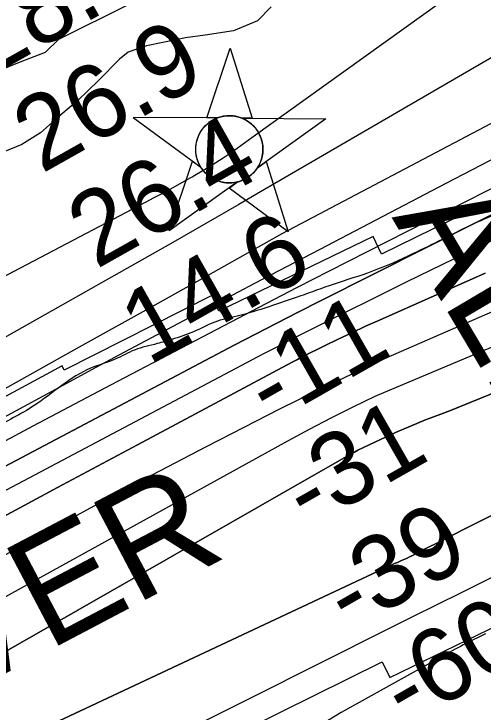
# Model space of a CAD drawing. Extents: x 3324104 to 3361979, y 612876 to 638273.
# Drawn here: x 3355279 to 3355706, y 622268 to 622903 of the extents above; entities that cross this region are included whole.
import ezdxf

# ---------------------------------------------------------------- set-up
doc = ezdxf.new("R2010")
doc.units = 0
for name, color, linetype in [('V-CHAN-NAID', 7, 'Continuous'), ('V-RIVR-EDGE', 7, 'Continuous'), ('V-RIVR-RANG', 7, 'Continuous'), ('V-RRAP-RVMT', 7, 'Continuous'), ('V-RRAP-RVMT-IDEN', 7, 'Continuous'), ('V-TOPO-DPTH', 7, 'Continuous'), ('V-TOPO-MAJR', 7, 'Continuous'), ('V-TOPO-MINR', 7, 'Continuous'), ('V-TOPO-WATR', 7, 'Continuous'), ('V-WETL-SWMP', 7, 'Continuous')]:
    doc.layers.add(name, color=color, linetype=linetype)

msp = doc.modelspace()

# ---------------------------------------------------------------- linework, layer by layer
at = {"layer": 'V-CHAN-NAID'}
for points in [[(3355464.16, 622808.58), (3355454.57, 622808.65), (3355475.7, 622872.14), (3355495.92, 622808.36), (3355486.34, 622808.43), (3355484.76, 622809.01), (3355482.67, 622809.63), (3355480.62, 622810.08), (3355478.59, 622810.38), (3355477.42, 622810.5), (3355475.89, 622810.58), (3355474.17, 622810.58), (3355472.8, 622810.51), (3355470.89, 622810.31), (3355469.52, 622810.09), (3355467.74, 622809.7), (3355466.21, 622809.28), (3355465.18, 622808.95)], [(3355464.16, 622808.58), (3355387.67, 622809.13), (3355449.23, 622763.73), (3355448.12, 622765.64), (3355447.31, 622767.26), (3355446.49, 622769.23), (3355445.79, 622771.29), (3355445.43, 622772.61), (3355445.06, 622774.24), (3355444.82, 622775.68), (3355444.63, 622777.28), (3355444.52, 622779.01), (3355444.51, 622780.6), (3355444.62, 622782.67), (3355444.8, 622784.29), (3355445.19, 622786.49), (3355445.68, 622788.41), (3355446.28, 622790.3), (3355446.93, 622791.98), (3355447.66, 622793.57), (3355448.47, 622795.1), (3355449.54, 622796.84), (3355450.57, 622798.31), (3355451.57, 622799.58), (3355452.57, 622800.72), (3355453.88, 622802.06), (3355454.93, 622803.03), (3355456.65, 622804.42), (3355457.86, 622805.29), (3355459.54, 622806.36), (3355461.27, 622807.31), (3355462.72, 622807.99)], [(3355486.34, 622808.43), (3355562.83, 622807.88), (3355500.63, 622763.36), (3355501.54, 622764.85), (3355502.52, 622766.7), (3355503.23, 622768.28), (3355503.97, 622770.24), (3355504.51, 622772.02), (3355504.91, 622773.66), (3355505.27, 622775.67), (3355505.46, 622777.25), (3355505.58, 622779.45), (3355505.55, 622781.51), (3355505.37, 622783.73), (3355505.1, 622785.49), (3355504.61, 622787.72), (3355503.97, 622789.86), (3355503.22, 622791.85), (3355502.57, 622793.29), (3355501.56, 622795.2), (3355500.5, 622796.93), (3355499.29, 622798.63), (3355498.03, 622800.17), (3355496.75, 622801.53), (3355495.12, 622803.07), (3355493.38, 622804.48), (3355491.7, 622805.65), (3355489.81, 622806.79), (3355488.34, 622807.55)], [(3355482.6, 622750.46), (3355420.39, 622705.93), (3355441.52, 622769.42), (3355449.23, 622763.73), (3355449.87, 622762.76), (3355451.25, 622760.9), (3355452.47, 622759.49), (3355453.93, 622757.99), (3355455.32, 622756.73), (3355456.77, 622755.58), (3355458.18, 622754.59), (3355459.86, 622753.56), (3355461.57, 622752.64), (3355463.36, 622751.83), (3355464.81, 622751.28), (3355466.44, 622750.75), (3355468.66, 622750.18), (3355470.19, 622749.9), (3355472.22, 622749.64), (3355473.75, 622749.54), (3355475.62, 622749.51), (3355477.31, 622749.59), (3355479.02, 622749.77), (3355480.92, 622750.08)], [(3355500.63, 622763.36), (3355508.42, 622768.94), (3355528.65, 622705.17), (3355474.8, 622744.88), (3355482.6, 622750.46), (3355484.26, 622750.93), (3355485.87, 622751.49), (3355488.03, 622752.41), (3355489.77, 622753.29), (3355491.63, 622754.4), (3355493.37, 622755.62), (3355494.92, 622756.86), (3355496.21, 622758.03), (3355497.59, 622759.45), (3355498.8, 622760.85), (3355499.92, 622762.32)]]:
    msp.add_lwpolyline(points, close=True, dxfattribs=at)
msp.add_circle((3355475.05, 622780.05), 30.54, dxfattribs=at)
at = {"layer": 'V-RIVR-EDGE'}
msp.add_spline([(3356051.95, 622889.63), (3356029.15, 622881.43), (3356012.46, 622875.66), (3355994.6, 622867.17), (3355977.52, 622859.07), (3355958.5, 622850.97), (3355948.4, 622843.24), (3355934.03, 622834.75), (3355904.12, 622817.76), (3355878.1, 622802.31), (3355856.74, 622790.34), (3355829.95, 622776.44), (3355805.11, 622765.65), (3355764.72, 622744.81), (3355744.14, 622733.61), (3355694.06, 622710.85), (3355668.43, 622698.12), (3355641.64, 622685), (3355605.15, 622669.19), (3355569.44, 622657.26), (3355539.17, 622646.47), (3355510.83, 622636.85), (3355482.11, 622628.39), (3355461.93, 622623.01), (3355442.52, 622614.14), (3355422.73, 622607.21), (3355409.53, 622603.36), (3355388.97, 622597.59), (3355371.88, 622589.49), (3355348.98, 622581.02), (3355297.71, 622547.02), (3355260.04, 622525.78), (3355211.1, 622494.49), (3355190.13, 622484.46), (3355184.7, 622482.92), (3355179.26, 622477.89), (3355174.21, 622475.58), (3355160.62, 622470.96), (3355143.54, 622463.63), (3355133.06, 622457.07), (3355125.67, 622450.49), (3355113.25, 622443.93), (3355096.93, 622433.11), (3355081.02, 622426.95), (3355064.32, 622419.23), (3355056.95, 622418.86), (3355048.8, 622414.62), (3355041.8, 622406.88), (3355036.76, 622406.5), (3355031.32, 622405.74), (3355027.05, 622404.2), (3355017.34, 622396.08), (3355010.74, 622394.93), (3355001.42, 622388.36), (3354988.6, 622379.09), (3354972.29, 622369.43), (3354947.44, 622356.31), (3354937.73, 622351.68), (3354926.08, 622343.56), (3354903.15, 622326.56), (3354891.11, 622318.06), (3354883.33, 622307.22), (3354879.44, 622304.12), (3354875.17, 622302.58), (3354867.8, 622299.11), (3354853.03, 622288.29), (3354842.54, 622279.01), (3354826.61, 622267.41), (3354807.2, 622259.71), (3354793.23, 622255.47), (3354765.68, 622249.73), (3354748.61, 622245.5), (3354734.63, 622239.33), (3354712.11, 622227.37), (3354697.74, 622218.87), (3354685.31, 622209.98), (3354640.65, 622184.5), (3354622.01, 622176.01), (3354616.19, 622175.25), (3354603.38, 622167.52), (3354578.92, 622157.11), (3354554.46, 622147.48), (3354537.39, 622142.87), (3354530.78, 622137.84), (3354500.11, 622122.79), (3354463.61, 622102.33), (3354417.79, 622078.79), (3354386.33, 622060.64), (3354340.11, 622032.44), (3354321.08, 622021.25), (3354284.96, 621998.84), (3354257, 621982.24), (3354217, 621958.68), (3354194.08, 621942.84), (3354176.99, 621931.63), (3354157.57, 621921.98), (3354141.64, 621910.39), (3354135.42, 621904.2), (3354130.36, 621897.62), (3354120.65, 621891.05), (3354103.96, 621882.95), (3354075.58, 621856.65), (3354044.89, 621835.39), (3354013.04, 621812.21), (3353971.47, 621781.67), (3353947.77, 621763.5), (3353941.17, 621763.52), (3353935.35, 621762.76), (3353929.53, 621760.06), (3353924.87, 621756.58), (3353920.59, 621751.55), (3353917.08, 621742.64), (3353910.48, 621741.49), (3353904.66, 621738.4), (3353893.78, 621731.06), (3353879.8, 621721.4), (3353866.19, 621708.64), (3353854.92, 621697.42), (3353843.26, 621687.75), (3353839.77, 621688.54), (3353831.23, 621686.23), (3353823.08, 621681.21), (3353818.03, 621677.34), (3353800.94, 621666.14), (3353790.85, 621663.06), (3353781.91, 621654.94), (3353777.63, 621651.85), (3353776.07, 621648.75), (3353775.67, 621643.71), (3353772.18, 621641), (3353755.87, 621632.13), (3353735.68, 621622.09), (3353718.58, 621608.17), (3353704.21, 621600.45), (3353694.12, 621596.6), (3353683.64, 621592.36), (3353671.21, 621584.25), (3353642.07, 621562.99), (3353598.95, 621534.01), (3353578.37, 621522.43), (3353556.23, 621507.75), (3353547.68, 621501.95), (3353525.93, 621489.21), (3353513.12, 621481.09), (3353497.18, 621468.34), (3353476.98, 621450.94), (3353453.28, 621436.65), (3353435.8, 621424.67), (3353404.72, 621401.09), (3353378.3, 621380.21), (3353361.59, 621368.62), (3353339.46, 621355.1), (3353319.65, 621342.35), (3353299.45, 621329.99), (3353283.54, 621324.6), (3353273.05, 621317.65), (3353254.77, 621295.98), (3353236.88, 621275.47), (3353219.39, 621258.83), (3353195.69, 621241.44), (3353168.49, 621221.34), (3353137.81, 621201.64), (3353112.17, 621185.03), (3353065.55, 621151.79), (3353022.05, 621122.82), (3352993.29, 621100.39), (3352956, 621073.34), (3352907.05, 621037.78), (3352853.8, 620991.77), (3352787.76, 620942.29), (3352749.68, 620913.3), (3352736.85, 620900.92), (3352733.34, 620892.79), (3352728.67, 620886.59), (3352718.96, 620881.19), (3352691.78, 620864.58), (3352660.31, 620841.78), (3352640.5, 620828.25), (3352623.39, 620811.23), (3352605.12, 620792.27), (3352593.46, 620783), (3352582.59, 620778.76), (3352566.29, 620771.43), (3352548.04, 620764.49), (3352522.41, 620750.98), (3352494.45, 620735.54), (3352482.41, 620727.04), (3352479.3, 620723.17), (3352476.96, 620717.36), (3352470.74, 620711.94), (3352455.99, 620707.33), (3352443.18, 620700.38), (3352419.1, 620685.7), (3352392.3, 620669.09), (3352362.78, 620650.94), (3352339.08, 620634.32), (3352315.38, 620615.38), (3352284.68, 620590.63), (3352258.65, 620571.31), (3352228.74, 620550.05), (3352193.39, 620527.65), (3352156.88, 620504.86), (3352131.63, 620487.47), (3352093.95, 620462.36), (3352049.28, 620432.99), (3351990.23, 620391.26), (3351936.63, 620357.26), (3351851.55, 620293.87), (3351833.29, 620281.51), (3351816.98, 620273.79), (3351794.06, 620257.95), (3351767.65, 620240.95), (3351719.86, 620206.17), (3351680.63, 620177.57), (3351657.32, 620160.56), (3351637.11, 620145.87), (3351623.13, 620135.44), (3351603.32, 620124.24), (3351588.57, 620120.01), (3351567.22, 620109.59), (3351552.08, 620103.43), (3351538.1, 620096.48), (3351523.73, 620086.43), (3351510.91, 620076.38), (3351503.52, 620069.81), (3351495.35, 620057.42), (3351486, 620042.32), (3351479.39, 620032.64), (3351469.67, 620022.58), (3351448.3, 620006.34), (3351431.59, 619994.75), (3351404.78, 619973.88), (3351377.97, 619951.84), (3351358.93, 619936.37), (3351332.12, 619915.5), (3351306.08, 619892.29), (3351274.58, 619858.25), (3351238.83, 619826.92), (3351215.12, 619805.65), (3351171.59, 619767.75), (3351145.54, 619739.51), (3351124.55, 619722.11), (3351105.9, 619707.81), (3351089.59, 619696.99), (3351079.49, 619691.2), (3351074.04, 619683.45), (3351058.1, 619666.43), (3351043.34, 619655.22), (3351015.36, 619633.96), (3350999.05, 619623.14), (3350992.05, 619617.34), (3350979.23, 619606.13), (3350966.01, 619594.53), (3350951.25, 619582.15), (3350935.7, 619567.84), (3350923.26, 619555.08), (3350910.05, 619544.25), (3350888.29, 619528.02), (3350846.74, 619504.08), (3350821.49, 619490.18), (3350811.39, 619483.61), (3350805.96, 619480.52), (3350800.9, 619473.16), (3350797.41, 619473.17), (3350793.92, 619474.35), (3350788.88, 619473.58), (3350786.93, 619472.04), (3350785.37, 619467.39), (3350785.36, 619462.73), (3350779.53, 619456.15), (3350765.93, 619445.72), (3350746.11, 619428.7), (3350722.4, 619408.98), (3350716.19, 619407.06), (3350713.08, 619403.96), (3350711.13, 619396.99), (3350708.79, 619391.57), (3350704.52, 619391.58), (3350693.26, 619385.79), (3350686.65, 619379.6), (3350679.64, 619368.37), (3350661.38, 619354.45), (3350648.56, 619344.4), (3350645.46, 619344.8), (3350638.47, 619339.39), (3350623.32, 619330.5), (3350616.33, 619326.26), (3350602.35, 619317.37), (3350598.83, 619308.85), (3350582.91, 619299.19), (3350553.77, 619276), (3350526.18, 619255.51), (3350493.55, 619231.94), (3350474.9, 619219.57), (3350474.5, 619213.76), (3350470.22, 619207.17), (3350458.96, 619202.55), (3350446.14, 619194.05), (3350441.09, 619189.79), (3350438.76, 619186.31), (3350434.48, 619180.89), (3350414.67, 619167.76), (3350401.46, 619159.26), (3350384.75, 619146.89), (3350369.6, 619133.74), (3350356.39, 619125.24), (3350350.95, 619119.05), (3350347.43, 619109.36), (3350338.1, 619097.75), (3350324.88, 619083.82), (3350308.55, 619069.9), (3350300.39, 619062.56), (3350296.13, 619062.57), (3350291.47, 619062.19), (3350274.77, 619050.6), (3350258.45, 619037.45), (3350251.84, 619032.81), (3350244.08, 619029.34), (3350233.61, 619028.21), (3350227.39, 619024.34), (3350220.39, 619016.99), (3350213, 619007.32), (3350202.12, 618996.87), (3350193.57, 618989.52), (3350179.6, 618985.29), (3350173.77, 618980.65), (3350164.84, 618977.96), (3350162.12, 618975.25), (3350159.39, 618971.38), (3350154.33, 618963.64), (3350145.78, 618953.19), (3350125.96, 618938.11), (3350102.66, 618923.05), (3350094.5, 618918.41), (3350086.34, 618913), (3350075.07, 618901.01), (3350064.19, 618892.12), (3350039.32, 618873.57), (3350021.84, 618861.59), (3350002.03, 618848.84), (3349991.94, 618844.21), (3349964.36, 618826.44), (3349938.72, 618807.11), (3349915.41, 618792.82), (3349892.5, 618778.92), (3349868.02, 618761.91), (3349852.49, 618753.03), (3349842.79, 618749.95), (3349830.35, 618739.13), (3349804.32, 618720.19), (3349777.9, 618697.76), (3349751.86, 618677.66), (3349729.72, 618661.43), (3349703.69, 618642.88), (3349678.84, 618629.75), (3349648.93, 618611.99), (3349624.46, 618594.99), (3349592.61, 618575.67), (3349570.48, 618564.87), (3349549.5, 618548.63), (3349505.21, 618518.11), (3349479.19, 618499.94), (3349471.42, 618494.53), (3349458.99, 618487.59), (3349438.4, 618472.12), (3349412.37, 618452.41), (3349379.73, 618429.61), (3349350.21, 618410.29), (3349303.2, 618374.73), (3349277.56, 618357.73), (3349263.97, 618347.29), (3349241.43, 618330.68), (3349226.67, 618319.85), (3349207.25, 618306.33), (3349193.17, 618293.54)], degree=3, dxfattribs=at)
at = {"layer": 'V-RRAP-RVMT'}
for p, q in [((3355738.26, 622746.21), (3355613.41, 622684.64)), ((3355605.67, 622700.74), (3355465.55, 622633.03)), ((3355613.41, 622684.64), (3355605.67, 622700.74)), ((3355459.07, 622647.23), (3355325.02, 622579.15)), ((3355465.55, 622633.03), (3355459.07, 622647.23)), ((3355323.07, 622583.3), (3355208.2, 622520.69)), ((3355325.02, 622579.15), (3355323.07, 622583.3)), ((3355620.97, 622299.85), (3355762.68, 622368.67)), ((3355481.97, 622248.79), (3355613.97, 622314.17)), ((3355613.97, 622314.17), (3355620.97, 622299.85))]:
    msp.add_line(p, q, dxfattribs=at)
at = {"layer": 'V-TOPO-DPTH'}
for points in [[(3356335.67, 623084.15), (3356302.73, 623070.5), (3356251.46, 623048.8), (3356244.29, 623045.67), (3356237.17, 623042.42), (3356230.12, 623039.01), (3356223.13, 623035.49), (3355758.71, 622794.29), (3355671.73, 622748.9), (3355557.21, 622689.08), (3355527.51, 622673.54), (3355497.83, 622657.99), (3355468.17, 622642.4), (3355438.52, 622626.79), (3355408.9, 622611.11), (3355379.32, 622595.37), (3355349.79, 622579.52), (3355320.3, 622563.61), (3354850.48, 622309.01)], [(3354836.25, 622258.22), (3354942.17, 622315.88), (3355008.38, 622351.76), (3355074.68, 622387.48), (3355141.11, 622422.95), (3355207.62, 622458.26), (3355479.38, 622601.88), (3355498.76, 622612.04), (3355518.18, 622622.13), (3355537.66, 622632.1), (3355557.18, 622642), (3355752.47, 622740.24), (3356228.06, 622962.18), (3356248.96, 622971.36), (3356269.92, 622980.36), (3356290.99, 622989.11), (3356312.14, 622997.68)], [(3354836.25, 622258.22), (3354942.17, 622315.88), (3355008.38, 622351.76), (3355074.68, 622387.48), (3355141.11, 622422.95), (3355207.62, 622458.26), (3355479.38, 622601.88), (3355498.76, 622612.04), (3355518.18, 622622.13), (3355537.66, 622632.1), (3355557.18, 622642), (3355752.47, 622740.24), (3356228.06, 622962.18), (3356248.96, 622971.36), (3356269.92, 622980.36), (3356290.99, 622989.11), (3356312.14, 622997.68)], [(3356356.71, 622871.23), (3355607.42, 622555.21), (3355587.3, 622545.5), (3355567.31, 622535.53), (3355547.51, 622525.18), (3355527.85, 622514.57), (3355145.77, 622303.66), (3355099.77, 622278.12), (3355053.84, 622252.44), (3355008.03, 622226.55), (3354962.3, 622200.52), (3354943.4, 622189.71), (3354907.16, 622169.01), (3354870.89, 622148.37), (3354834.57, 622127.8)], [(3356356.71, 622871.23), (3355607.42, 622555.21), (3355587.3, 622545.5), (3355567.31, 622535.53), (3355547.51, 622525.18), (3355527.85, 622514.57), (3355145.77, 622303.66), (3355099.77, 622278.12), (3355053.84, 622252.44), (3355008.03, 622226.55), (3354962.3, 622200.52), (3354943.4, 622189.71), (3354907.16, 622169.01), (3354870.89, 622148.37), (3354834.57, 622127.8)], [(3354869.67, 622093.49), (3354882.89, 622101.03), (3354896.1, 622108.59), (3354909.31, 622116.16), (3354922.5, 622123.75), (3355585.66, 622503.26), (3355588.77, 622504.83), (3355591.9, 622506.37), (3355612.47, 622516.2), (3355625.99, 622522.43), (3355639.62, 622528.39), (3355653.41, 622533.96), (3355667.31, 622539.27), (3355675.94, 622542.43), (3356355.15, 622819.11)], [(3354869.67, 622093.49), (3354882.89, 622101.03), (3354896.1, 622108.59), (3354909.31, 622116.16), (3354922.5, 622123.75), (3355585.66, 622503.26), (3355588.77, 622504.83), (3355591.9, 622506.37), (3355612.47, 622516.2), (3355625.99, 622522.43), (3355639.62, 622528.39), (3355653.41, 622533.96), (3355667.31, 622539.27), (3355675.94, 622542.43), (3356355.15, 622819.11)], [(3356339.41, 622761.82), (3356303.08, 622743.54), (3355688.57, 622434.57), (3355680.29, 622430.4), (3355672, 622426.23), (3355663.72, 622422.05), (3355655.43, 622417.88), (3355639.7, 622409.94), (3355639.28, 622409.73), (3355635.97, 622408.1), (3355631.58, 622406.06), (3355627.82, 622404.46), (3355625.2, 622403.34), (3355622.57, 622402.23), (3355619.95, 622401.11), (3354892.23, 622059.54), (3354561.97, 621866.56)], [(3354561.97, 621866.56), (3354892.23, 622059.54), (3355619.95, 622401.11), (3355622.57, 622402.23), (3355625.2, 622403.34), (3355627.82, 622404.46), (3355631.58, 622406.06), (3355635.97, 622408.1), (3355639.28, 622409.73), (3355639.7, 622409.94), (3355655.43, 622417.88), (3355663.72, 622422.05), (3355672, 622426.23), (3355680.29, 622430.4), (3355688.57, 622434.57), (3356303.08, 622743.54), (3356339.41, 622761.82)], [(3354862.73, 622224.17), (3354893.41, 622241.04), (3355101.28, 622354.64), (3355173.7, 622394.08), (3355246.19, 622433.38), (3355318.79, 622472.47), (3355391.46, 622511.42), (3355532.01, 622586.48), (3355534.48, 622587.78), (3355536.95, 622589.07), (3355539.43, 622590.34), (3355541.92, 622591.59), (3355561.57, 622601.36), (3355573.93, 622607.41), (3355586.35, 622613.35), (3355598.84, 622619.12), (3355611.38, 622624.79), (3355707.62, 622667.52)], [(3355707.62, 622667.52), (3355611.38, 622624.79), (3355598.84, 622619.12), (3355586.35, 622613.35), (3355573.93, 622607.41), (3355561.57, 622601.36), (3355541.92, 622591.59), (3355539.43, 622590.34), (3355536.95, 622589.07), (3355534.48, 622587.78), (3355532.01, 622586.48), (3355391.46, 622511.42), (3355318.79, 622472.47), (3355246.19, 622433.38), (3355173.7, 622394.08), (3355101.28, 622354.64), (3354893.41, 622241.04), (3354862.73, 622224.17)]]:
    msp.add_lwpolyline(points, dxfattribs=at)
at = {"layer": 'V-TOPO-MAJR'}
for points in [[(3357036.92, 623475.26), (3356113.56, 623231.69), (3356095.43, 623221.25), (3355508.41, 622799.91), (3355495.54, 622790.38), (3355482.29, 622780.9), (3355475.84, 622776.4), (3355469.31, 622772), (3355462.68, 622767.76), (3355455.99, 622763.62), (3355445.14, 622757.1), (3355443.81, 622756.31), (3355441.13, 622754.77), (3355439.78, 622754.01), (3355428.07, 622747.56), (3355420.85, 622743.6), (3355413.62, 622739.68), (3355406.36, 622735.8), (3355399.09, 622731.95), (3354773.79, 622403.37)], [(3356363.42, 622701.14), (3356238.51, 622643.15), (3356154.47, 622603.82), (3356070.6, 622564.16), (3355986.97, 622524), (3355903.5, 622483.49), (3355707.67, 622387.73), (3355685.6, 622376.89), (3355663.56, 622366.01), (3355641.54, 622355.06), (3355619.56, 622344.06), (3355493.58, 622280.79), (3355408.69, 622237.98), (3355154.67, 622108.29), (3355002.74, 622029.92), (3354980.45, 622018.04), (3354958.38, 622005.78), (3354936.64, 621992.94), (3354915.12, 621979.71), (3354573.65, 621763.5)]]:
    msp.add_lwpolyline(points, dxfattribs=at)
at = {"layer": 'V-TOPO-MINR'}
for points in [[(3356897.15, 623379.54), (3356208.04, 623146.33), (3356197.6, 623141.72), (3356187.28, 623136.86), (3356177.14, 623131.63), (3356167.13, 623126.14), (3356057.26, 623063.3), (3355992.46, 623026.12), (3355503.51, 622741.36), (3355483.59, 622729.78), (3355463.63, 622718.26), (3355443.62, 622706.82), (3355423.58, 622695.43), (3355095.26, 622509.91), (3355039.89, 622478.7), (3354984.5, 622447.55), (3354929.04, 622416.5), (3354873.55, 622385.51), (3354782.39, 622334.72)], [(3356411.3, 623150.86), (3356267.2, 623091.83), (3356244.27, 623082.08), (3356221.52, 623071.94), (3355522.88, 622703.26), (3355484.45, 622681.58), (3355445.96, 622659.98), (3355407.44, 622638.44), (3355338.73, 622600.11), (3355265.77, 622559.55), (3355192.74, 622519.12), (3355119.6, 622478.9), (3355046.39, 622438.81), (3354791.37, 622299.63)], [(3356335.67, 623084.15), (3356302.73, 623070.5), (3356251.46, 623048.8), (3356244.29, 623045.67), (3356237.17, 623042.42), (3356230.12, 623039.01), (3356223.13, 623035.49), (3355758.71, 622794.29), (3355671.73, 622748.9), (3355557.21, 622689.08), (3355527.51, 622673.54), (3355497.83, 622657.99), (3355468.17, 622642.4), (3355438.52, 622626.79), (3355408.9, 622611.11), (3355379.32, 622595.37), (3355349.79, 622579.52), (3355320.3, 622563.61), (3354850.48, 622309.01)], [(3356315.29, 623036.86), (3356284.19, 623024.53), (3356253.24, 623011.84), (3356222.51, 622998.62), (3356191.93, 622985.04), (3356161.57, 622970.99), (3356131.33, 622956.66), (3356101.28, 622941.94), (3355565.09, 622668.91), (3355536.63, 622654.34), (3355508.22, 622639.68), (3355367.05, 622565.5), (3355296.59, 622528.19), (3355226.22, 622490.69), (3355155.99, 622452.94), (3355085.85, 622415.02), (3354843.25, 622283.25)], [(3356334.77, 622972.5), (3356297.09, 622957.06), (3356291.01, 622954.54), (3356284.95, 622951.99), (3356278.9, 622949.38), (3356272.87, 622946.75), (3355799.27, 622737.1), (3355744.45, 622711.81), (3355690, 622685.77), (3355635.78, 622659.23), (3355549.42, 622616.19), (3355538.58, 622610.74), (3355527.77, 622605.23), (3355517, 622599.65), (3355506.25, 622594), (3354977.66, 622313.9), (3354951.13, 622299.79), (3354924.64, 622285.61), (3354898.19, 622271.36), (3354871.77, 622257.04), (3354829.53, 622234.06)], [(3356315.92, 622893.42), (3356291.2, 622883.25), (3356266.45, 622873.19), (3355619.49, 622590.99), (3355586.37, 622575.64), (3355553.41, 622559.95), (3355520.7, 622543.76), (3355488.15, 622527.23), (3355453.94, 622509.52), (3355404.55, 622483.64), (3355355.32, 622457.43), (3355306.36, 622430.74), (3355257.58, 622403.72), (3354896.37, 622201.38), (3354874.32, 622189), (3354852.28, 622176.59)], [(3356356.71, 622871.23), (3355607.42, 622555.21), (3355587.3, 622545.5), (3355567.31, 622535.53), (3355547.51, 622525.18), (3355527.85, 622514.57), (3355145.77, 622303.66), (3355099.77, 622278.12), (3355053.84, 622252.44), (3355008.03, 622226.55), (3354962.3, 622200.52), (3354943.4, 622189.71), (3354907.16, 622169.01), (3354870.89, 622148.37), (3354834.57, 622127.8)], [(3356355.15, 622819.11), (3355675.94, 622542.43), (3355667.31, 622539.27), (3355653.41, 622533.96), (3355639.62, 622528.39), (3355625.99, 622522.43), (3355612.47, 622516.2), (3355591.9, 622506.37), (3355588.77, 622504.83), (3355585.66, 622503.26), (3354922.5, 622123.75), (3354909.31, 622116.16), (3354896.1, 622108.59), (3354882.89, 622101.03), (3354869.67, 622093.49)], [(3356339.41, 622761.82), (3356303.08, 622743.54), (3355688.57, 622434.57), (3355680.29, 622430.4), (3355672, 622426.23), (3355663.72, 622422.05), (3355655.43, 622417.88), (3355639.7, 622409.94), (3355639.28, 622409.73), (3355635.97, 622408.1), (3355631.58, 622406.06), (3355627.82, 622404.46), (3355625.2, 622403.34), (3355622.57, 622402.23), (3355619.95, 622401.11), (3354892.23, 622059.54), (3354561.97, 621866.56)], [(3355707.62, 622667.52), (3355611.38, 622624.79), (3355598.84, 622619.12), (3355586.35, 622613.35), (3355573.93, 622607.41), (3355561.57, 622601.36), (3355541.92, 622591.59), (3355539.43, 622590.34), (3355536.95, 622589.07), (3355534.48, 622587.78), (3355532.01, 622586.48), (3355391.46, 622511.42), (3355318.79, 622472.47), (3355246.19, 622433.38), (3355173.7, 622394.08), (3355101.28, 622354.64), (3354893.41, 622241.04), (3354862.73, 622224.17)], [(3355707.95, 622339.39), (3355690.02, 622330.62), (3355687.53, 622329.38), (3355685.06, 622328.12), (3355682.62, 622326.82), (3355680.18, 622325.5), (3355576.61, 622268.09), (3355558.88, 622257.02), (3355542.05, 622244.83), (3355526.57, 622230.96), (3355512, 622215.97), (3355507.55, 622203.53), (3355507.62, 622192.72), (3355514.47, 622184.36), (3355525.85, 622177.64), (3355565.38, 622171.33), (3355582.19, 622169.86), (3355598.88, 622169.93)]]:
    msp.add_lwpolyline(points, dxfattribs=at)
at = {"layer": 'V-TOPO-WATR'}
msp.add_lwpolyline([(3356312.14, 622997.68), (3356290.99, 622989.11), (3356269.92, 622980.36), (3356248.96, 622971.36), (3356228.06, 622962.18), (3355752.47, 622740.24), (3355557.18, 622642), (3355537.66, 622632.1), (3355518.18, 622622.13), (3355498.76, 622612.04), (3355479.38, 622601.88), (3355207.62, 622458.26), (3355141.11, 622422.95), (3355074.68, 622387.48), (3355008.38, 622351.76), (3354942.17, 622315.88), (3354836.25, 622258.22)], dxfattribs=at)
at = {"layer": 'V-WETL-SWMP'}
for points in [[(3354855.52, 622632.74), (3354954.31, 622674.79), (3354978.85, 622684.1), (3355000.65, 622693.36), (3355022.45, 622702.63), (3355037.94, 622720.71), (3355052.14, 622733.29), (3355070.57, 622739.07), (3355097.21, 622745.67), (3355112.21, 622751.39), (3355137.2, 622775.8), (3355150.08, 622785.61), (3355180.76, 622797.07), (3355220.26, 622814.85), (3355249.98, 622843.45), (3355266.31, 622851.94), (3355287.44, 622860.51), (3355307.89, 622868.38), (3355320.04, 622880.24), (3355384.01, 622912.13)], [(3355512.94, 622909.49), (3355500.79, 622896.95), (3355478.99, 622887.69), (3355452.99, 622883.84), (3355435.19, 622881.5), (3355414.68, 622877.05), (3355399.64, 622874.07), (3355383.27, 622868.32), (3355375.14, 622862.02), (3355356.25, 622842.51), (3355337.33, 622824.37), (3355319.73, 622809.69), (3355303.5, 622795.03), (3355286.53, 622784.46), (3355269.49, 622777.33)]]:
    msp.add_lwpolyline(points, dxfattribs=at)

# ---------------------------------------------------------------- texts
at = {"layer": 'V-CHAN-NAID'}
msp.add_text('ALHAMBRA RANGE D FRONT (189.4)', height=100, rotation=300.6244, dxfattribs=at).set_placement((3355622.33, 622718.28))
at = {"layer": 'V-RIVR-RANG'}
for s, rotation, p in [('28.7', 29.43833, (3355255.32, 622844.62)), ('26.9', 29.43833, (3355304.45, 622757.52)), ('26.4', 29.43833, (3355354.05, 622670.68)), ('14.6', 29.43833, (3355401.8, 622582.81)), ('-11', 29.72142, (3355512.31, 622530.06)), ('-31', 29.72142, (3355546.55, 622434.46)), ('-39', 29.72142, (3355584.01, 622340.69)), ('-60', 29.72142, (3355635.66, 622255.03)), ('-60', 29.72142, (3355685.02, 622168.07))]:
    msp.add_text(s, height=67, rotation=rotation, dxfattribs=at).set_placement(p)
at = {"layer": 'V-RRAP-RVMT-IDEN'}
msp.add_text('RIVER', height=100, rotation=27.78858, dxfattribs=at).set_placement((3355112.94, 622219.77))

doc.saveas('drawing.dxf')
